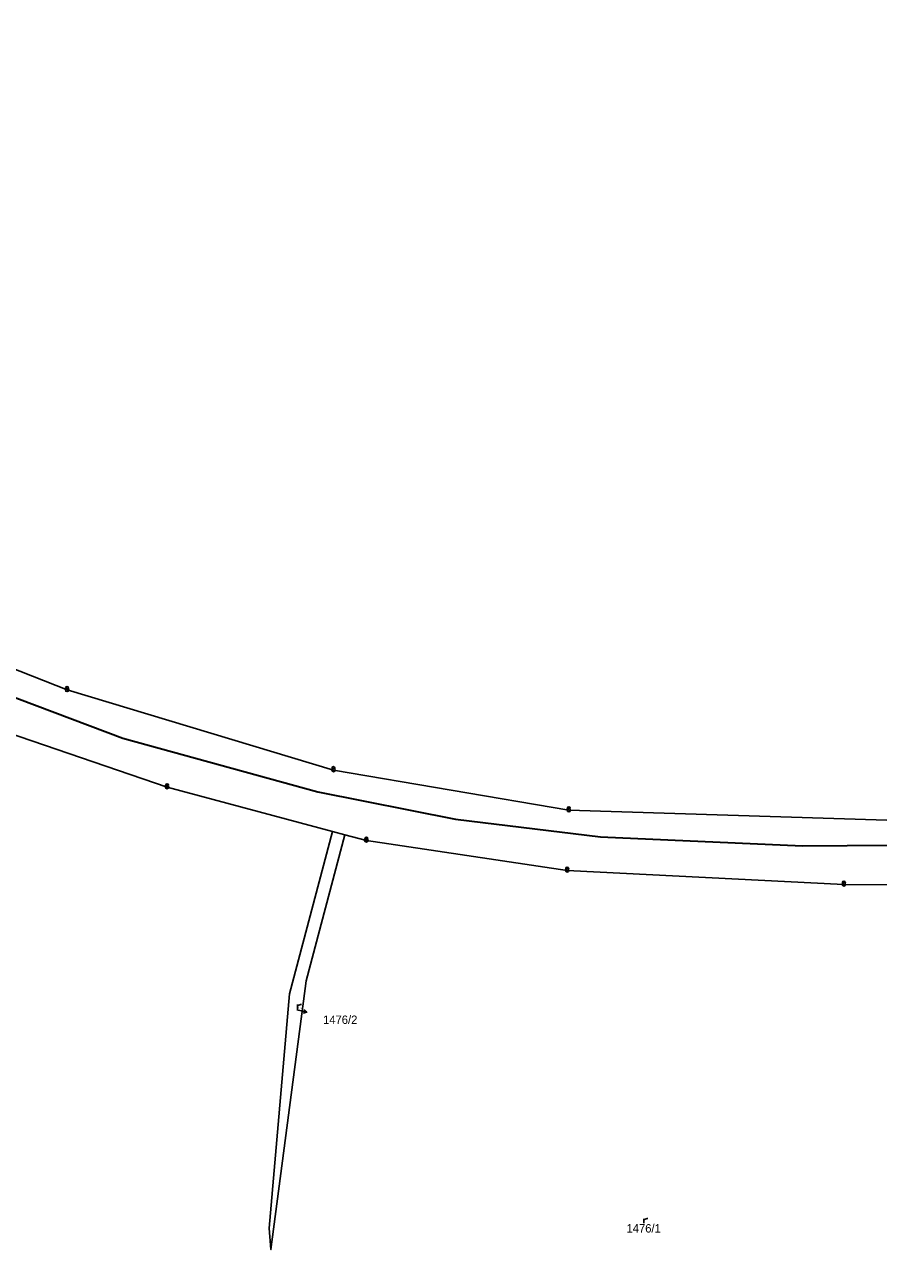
# Model space of a CAD drawing. Extents: x -871901 to -870967, y -1075952 to -1074892.
# Drawn here: x -871711.5 to -871609.8, y -1075317.6 to -1075171.7 of the extents above; entities that cross this region are included whole.
import ezdxf

# ---------------------------------------------------------------- set-up
doc = ezdxf.new("R2010")
doc.units = 0
doc.header["$LTSCALE"] = 0.4
for name, color, linetype, lineweight in [('1', 7, 'Continuous', 25), ('10', 7, 'Continuous', 35), ('16', 7, 'Continuous', 25), ('24', 7, 'Continuous', 25), ('25', 7, 'Continuous', 25)]:
    doc.layers.add(name, color=color, linetype=linetype, lineweight=lineweight)
doc.layers.add('18', color=7, linetype='Continuous')

msp = doc.modelspace()

# ---------------------------------------------------------------- linework, layer by layer
at = {"layer": '1'}
for points in [[(-871846.94, -1075171.67), (-871815.83, -1075191.94), (-871796.55, -1075203.2), (-871765.31, -1075221.39), (-871734.8, -1075238.65), (-871721.92, -1075244.81), (-871706.47, -1075250.92), (-871674.71, -1075260.45), (-871646.68, -1075265.23), (-871608.79, -1075266.42), (-871553.79, -1075265.47), (-871523.09, -1075265.22), (-871491.97, -1075267.91), (-871467.05, -1075273.87), (-871444.01, -1075283.21), (-871377.38, -1075316.93)], [(-871694.55, -1075262.49), (-871718.03, -1075254.49), (-871740.23, -1075244.04), (-871800.49, -1075209), (-871829.16, -1075194.06)], [(-871694.55, -1075262.49), (-871674.82, -1075267.77), (-871673.37, -1075268.15), (-871670.8, -1075268.84)], [(-871673.37, -1075268.15), (-871677.99, -1075285.55), (-871682.18, -1075317.55), (-871682.38, -1075314.99), (-871679.95, -1075287.1), (-871674.82, -1075267.77)], [(-871565.58, -1075274.43), (-871613.89, -1075274.07), (-871646.86, -1075272.41), (-871670.8, -1075268.84)]]:
    msp.add_lwpolyline(points, dxfattribs=at)
at = {"layer": '10'}
msp.add_lwpolyline([(-871838.74, -1075182), (-871771.68, -1075221.29), (-871743.32, -1075237.24), (-871725.75, -1075246.25), (-871714.22, -1075251.23), (-871699.81, -1075256.65), (-871676.57, -1075263.06), (-871660.16, -1075266.31), (-871642.88, -1075268.42), (-871618.84, -1075269.48), (-871586.98, -1075269.26), (-871550.47, -1075268.77), (-871530.68, -1075268.88), (-871514.5, -1075269.55), (-871500.36, -1075271.03), (-871487.52, -1075273.3), (-871475.72, -1075276.29), (-871459.68, -1075281.62), (-871443.06, -1075288.59)], dxfattribs=at)
at = {"layer": '16'}
msp.add_line((-871679.08, -1075289.02), (-871677.91, -1075289.289), dxfattribs=at)
msp.add_lwpolyline([(-871678.255, -1075289.005), (-871677.91, -1075289.289), (-871678.345, -1075289.394)], dxfattribs=at)
at = {"layer": '24'}
for centre, radius in [((-871706.4695, -1075250.9195), 0.2005), ((-871706.4695, -1075250.9195), 0.00851), ((-871674.7095, -1075260.4495), 0.2005), ((-871674.7095, -1075260.4495), 0.00851), ((-871694.5495, -1075262.4895), 0.2005), ((-871694.5495, -1075262.4895), 0.00851), ((-871646.6795, -1075265.2295), 0.2005), ((-871646.6795, -1075265.2295), 0.00851), ((-871670.7995, -1075268.8395), 0.2005), ((-871670.7995, -1075268.8395), 0.00851), ((-871646.8595, -1075272.4095), 0.2005), ((-871646.8595, -1075272.4095), 0.00851), ((-871613.8895, -1075274.0695), 0.2005), ((-871613.8895, -1075274.0695), 0.00851)]:
    msp.add_circle(centre, radius, dxfattribs=at)
for centre in [(-871706.4698, -1075250.6936), (-871674.7098, -1075260.2236), (-871694.5498, -1075262.2636), (-871646.6798, -1075265.0036), (-871670.7998, -1075268.6136), (-871646.8598, -1075272.1836), (-871613.8898, -1075273.8436)]:
    msp.add_arc(centre, 0.1746, 328.19485, 209.95045, dxfattribs=at)
at = {"layer": '25'}
for p, q in [((-871679, -1075288.91), (-871679, -1075288.389)), ((-871637.72, -1075314.4), (-871637.72, -1075313.879))]:
    msp.add_line(p, q, dxfattribs=at)
for points in [[(-871679, -1075288.553), (-871678.928, -1075288.482), (-871678.849, -1075288.437), (-871678.737, -1075288.407), (-871678.632, -1075288.388), (-871678.519, -1075288.381)], [(-871637.72, -1075314.043), (-871637.648, -1075313.972), (-871637.569, -1075313.927), (-871637.457, -1075313.897), (-871637.352, -1075313.878), (-871637.239, -1075313.871)]]:
    msp.add_lwpolyline(points, dxfattribs=at)

# ---------------------------------------------------------------- texts
at = {"layer": '16'}
msp.add_text('1476/2', height=1, dxfattribs=at).set_placement((-871675.96, -1075290.69))
at = {"layer": '18'}
for s, height, p in [('1476/2', 0.1, (-871678.88, -1075288.82)), ('1476/1', 1, (-871639.8, -1075315.53))]:
    msp.add_text(s, height=height, dxfattribs=at).set_placement(p)

doc.saveas('drawing.dxf')
